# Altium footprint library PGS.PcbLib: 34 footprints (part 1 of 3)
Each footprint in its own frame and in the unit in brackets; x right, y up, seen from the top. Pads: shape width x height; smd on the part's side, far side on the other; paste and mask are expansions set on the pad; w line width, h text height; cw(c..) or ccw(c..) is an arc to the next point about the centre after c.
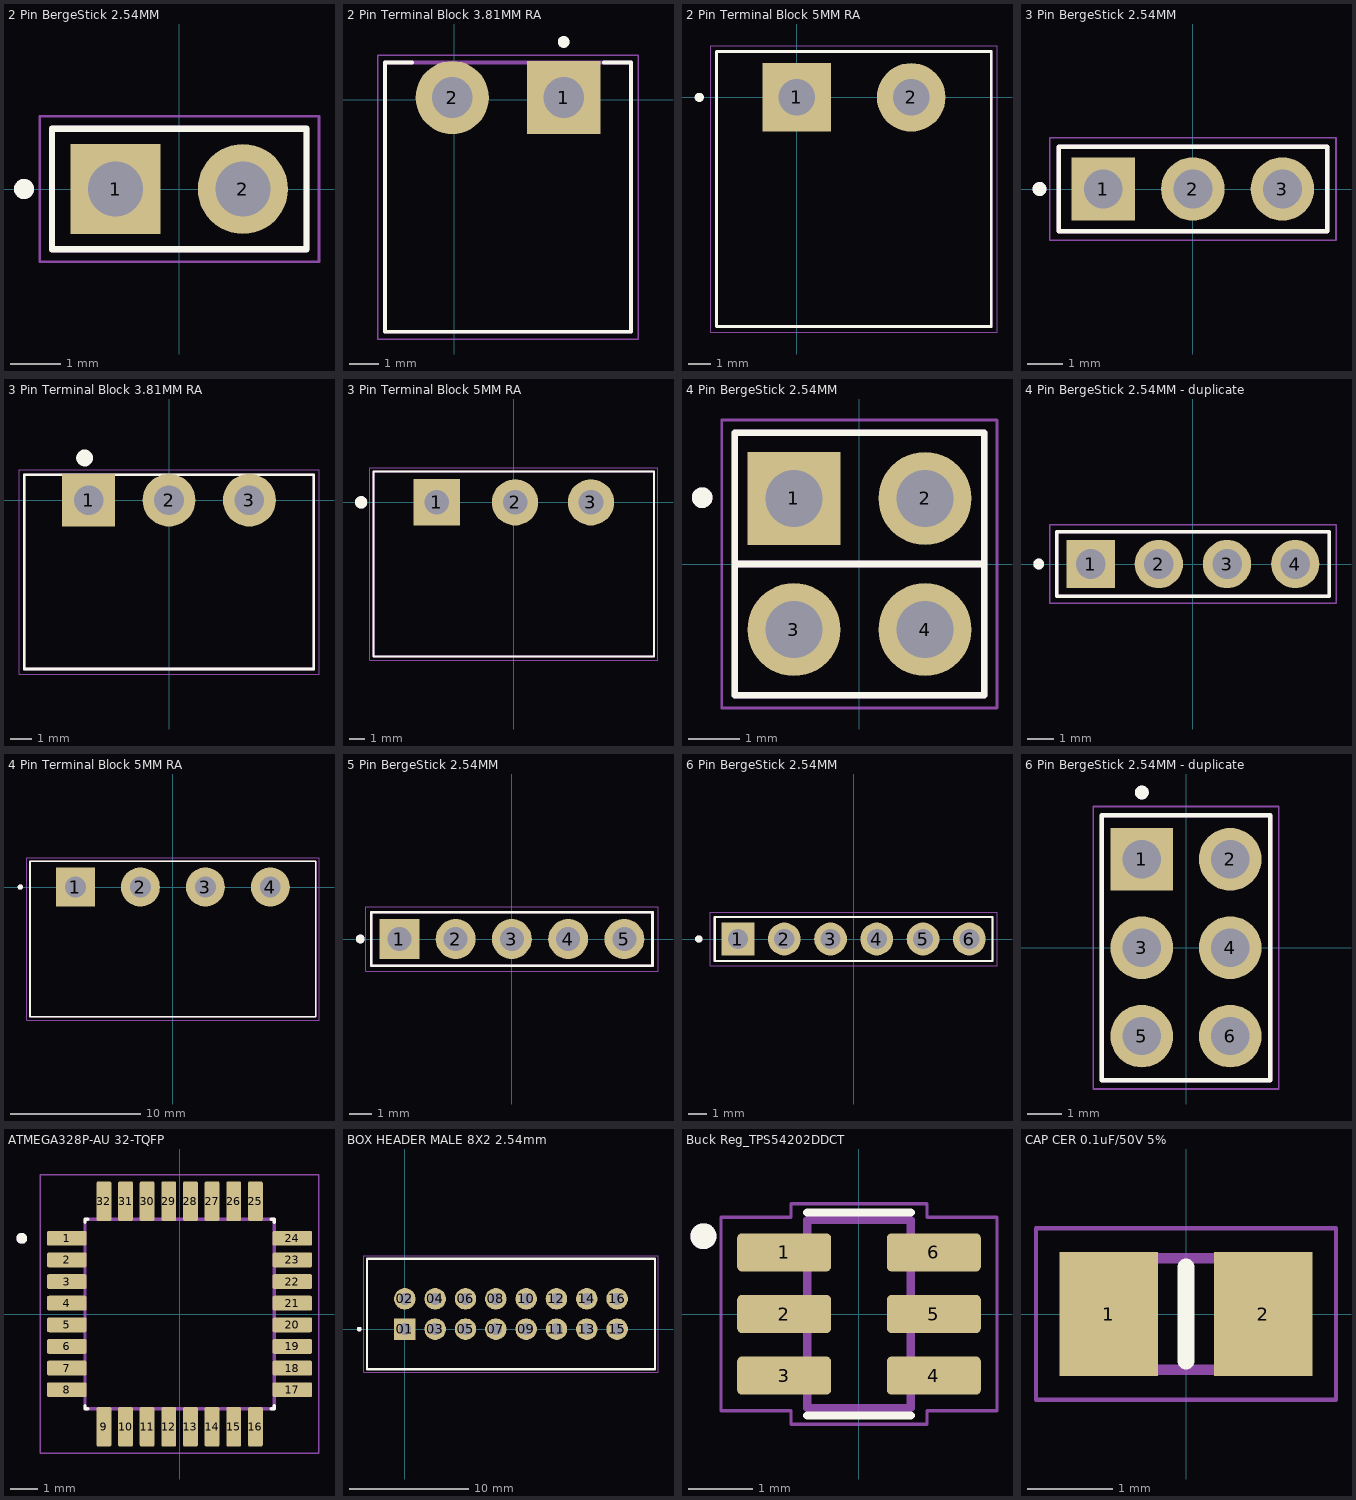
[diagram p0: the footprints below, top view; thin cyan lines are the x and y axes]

## 2 Pin BergeStick 2.54MM [mm] "2 Pin 2Pos THT S/T BergeStick 2.54MM Amphenol 68000-402HLF 3A AMPHENOL_68000-402HLF"
height 10.8
pads (2):
  rect 1.8x1.8 hole 1.1: 1(-1.27,0)
  round 1.8 hole 1.1: 2(1.27,0)
Top Overlay:
  circle w0.2: c-3.1,0 r0.1
  lines w0.127: -2.54,-1.205 2.54,-1.205 2.54,1.205 -2.54,1.205 -2.54,-1.205
Mechanical 13:
  circle w0.2: c-3.1,0 r0.1
  lines w0.127: -2.54,-1.205 2.54,-1.205 2.54,1.205 -2.54,1.205 -2.54,-1.205
Mechanical 15:
  lines w0.05: -2.79,-1.455 2.79,-1.455 2.79,1.455 -2.79,1.455 -2.79,-1.455
3D body "step_temp.STEP": height 8.39, standoff -2.41, extent -2.54,-1.205 2.54,1.205

## 2 Pin Terminal Block 3.81MM RA [mm] "2 Pin Terminal Block HDR 3.81MM THT RA TBP02R138102BE"
height 7.2
pads (2):
  rect 2.5x2.5 hole 1.4: 1(3.734,0.076)
  round 2.5 hole 1.4: 2(-0.076,0.076)
Top Overlay:
  circle w0.2: c3.734,1.976 r0.1
  lines w0.127: -1.446,1.276 -2.376,1.276 -2.376,-7.924 6.034,-7.924 6.034,1.276 5.104,1.276
Mechanical 13:
  circle w0.2: c3.734,1.976 r0.1
  lines w0.127: -2.376,-7.924 6.034,-7.924 6.034,1.276 -2.376,1.276 -2.376,-7.924
Mechanical 15:
  lines w0.05: -2.626,-8.174 6.284,-8.174 6.284,1.526 -2.626,1.526 -2.626,-8.174
3D body "step_temp.STEP": height 7.2, standoff -3.5, extent -2.39,-7.953 6.02,1.247

## 2 Pin Terminal Block 5MM RA [mm] "2 Pin Terminal Block HDR 5MM THT RA_OQ0271510000G"
height 8.5
pads (2):
  rect 3x3 hole 1.6: 1(0,0)
  round 3 hole 1.6: 2(5,0)
Top Overlay:
  circle w0.2: c-4.25,0 r0.1
  lines w0.127: -3.5,-10 -3.5,2 8.5,2 8.5,-10 -3.5,-10
Mechanical 13:
  circle w0.2: c-4.25,0 r0.1
  lines w0.127: -3.5,-10 -3.5,2 8.5,2 8.5,-10 -3.5,-10
Mechanical 15:
  lines w0.05: -3.75,-10.25 -3.75,2.25 8.75,2.25 8.75,-10.25 -3.75,-10.25
3D body "step_temp.STEP": height 8.5, standoff -3.5, extent -3.5,-10 8.5,2

## 3 Pin BergeStick 2.54MM [mm] "3 Pin 3Pos THT S/T BergeStick 2.54MM Amphenol 68001-403HLF 3A"
height 8.58
pads (3):
  rect 1.8x1.8 hole 1.1: 1(-2.54,0)
  round 1.8 hole 1.1: 2(0,0) 3(2.54,0)
Top Overlay:
  circle w0.2: c-4.35,0 r0.1
  lines w0.127: -3.81,-1.205 -3.81,1.205 3.81,1.205 3.81,-1.205 -3.81,-1.205
Mechanical 13:
  circle w0.2: c-4.35,0 r0.1
  lines w0.127: -3.81,-1.205 -3.81,1.205 3.81,1.205 3.81,-1.205 -3.81,-1.205
Mechanical 15:
  lines w0.05: -4.06,-1.455 -4.06,1.455 4.06,1.455 4.06,-1.455 -4.06,-1.455
3D body "step_temp.STEP": height 8.38, standoff -3.05, extent -3.81,-1.205 3.81,1.205

## 3 Pin Terminal Block 3.81MM RA [mm] "3 Pin Terminal Block HDR 3.81MM THT RA 284513-3"
pads (3):
  rect 2.5x2.5 hole 1.4: 1(-3.81,0)
  round 2.5 hole 1.4: 2(0,0) 3(3.81,0)
Top Overlay:
  circle w0.4: c-4,2 r0.2
  lines w0.127: -6.86,-8 -6.86,1.2 6.86,1.2 6.86,-8 -6.86,-8
Mechanical 13:
  lines w0.127: -6.86,-8 6.86,-8 6.86,1.2 -6.86,1.2 -6.86,-8
Mechanical 15:
  lines w0.05: -7.11,-8.25 7.11,-8.25 7.11,1.45 -7.11,1.45 -7.11,-8.25
3D body "step_temp.STEP": height 7.3, standoff -3.4, extent -6.86,-8.001 6.86,1.199

## 3 Pin Terminal Block 5MM RA [mm] "3 Pin Terminal Block HDR 5MM THT RA 231-433_001-000"
pads (3):
  rect 3x3 hole 1.6: 1(-5,0)
  round 3 hole 1.6: 2(0.08,0) 3(5,0)
Top Overlay:
  circle w0.4: c-9.91,0 r0.2
  lines w0.127: -9.1,-10 -9.1,2 9.1,2 9.1,-10 -9.1,-10
Mechanical 13:
  circle w0.4: c-9.906,0 r0.2
  lines w0.127: -9.1,-10 9.1,-10 9.1,2 -9.1,2 -9.1,-10
Mechanical 15:
  lines w0.05: -9.35,-10.25 -9.35,2.25 9.35,2.25 9.35,-10.25 -9.35,-10.25
3D body "2342079-3--3DModel-STEP-1.STEP": height 8.97, standoff -2.28, extent -8.418,-10.064 8.382,1.936

## 4 Pin BergeStick 2.54MM [mm] "4 Pin 2X2Pos THT S/T BergeStick 2.54MM Amphenol 67997-104HLF 3A AMPHENOL_67997-104HLF"
pads (4):
  rect 1.8x1.8 hole 1.1: 1(-1.27,1.27)
  round 1.8 hole 1.1: 2(1.27,1.27) 3(-1.27,-1.27) 4(1.27,-1.27)
Top Overlay:
  circle w0.2: c-3.048,1.285 r0.1
  lines w0.127: -2.413,0 2.413,0 ; -2.415,-2.54 2.415,-2.54 2.415,2.54 -2.415,2.54 -2.415,-2.54
Mechanical 13:
  circle w0.2: c-3.048,1.285 r0.1
  lines w0.127: -2.413,0 2.413,0 ; -2.415,-2.54 2.415,-2.54 ; -2.415,-2.54 -2.415,2.54 ; -2.415,-2.54 2.415,-2.54 ; -2.415,2.54 2.415,2.54 ; -2.415,2.54 2.415,2.54 ; 2.415,-2.54 2.415,2.54 ; 2.415,-2.54 2.415,2.54
Mechanical 15:
  lines w0.05: -2.665,-2.79 2.665,-2.79 2.665,2.79 -2.665,2.79 -2.665,-2.79
3D body "step_temp.STEP": height 8.38, standoff -3.05, extent -2.415,-2.54 2.415,2.54

## 4 Pin BergeStick 2.54MM - duplicate [mm] "4 Pin 4Pos THT S/T BergeStick 2.54MM Amphenol 68001-104HLF 3A AMPHENOL_68001-104HLF"
height 8.89
pads (4):
  rect 1.8x1.8 hole 1.1: 1(-3.81,0)
  round 1.8 hole 1.1: 2(-1.27,0) 3(1.27,0) 4(3.81,0)
Top Overlay:
  circle w0.2: c-5.75,0 r0.1
  lines w0.127: -5.08,-1.205 -5.08,1.205 5.08,1.205 5.08,-1.205 -5.08,-1.205
Mechanical 13:
  circle w0.2: c-5.75,0 r0.1
  lines w0.127: -5.08,-1.205 -5.08,1.205 5.08,1.205 5.08,-1.205 -5.08,-1.205
Mechanical 15:
  lines w0.05: -5.33,-1.455 -5.33,1.455 5.33,1.455 5.33,-1.455 -5.33,-1.455
3D body "step_temp.STEP": height 8.38, standoff -3.05, extent -5.08,-1.205 5.08,1.205

## 4 Pin Terminal Block 5MM RA [mm] "4 Pin Terminal Block HDR 5MM THT RA OQ0471510000G"
pads (4):
  rect 3x3 hole 1.6: 1(-7.5,0)
  round 3 hole 1.6: 2(-2.5,0) 3(2.5,0) 4(7.5,0)
Top Overlay:
  circle w0.2: c-11.75,0 r0.1
  lines w0.127: -11,-10 -11,2 11,2 11,-10 -11,-10
Mechanical 13:
  circle w0.2: c-11.75,0 r0.1
  lines w0.127: -11,-10 -11,2 11,2 11,-10 -11,-10
Mechanical 15:
  lines w0.05: -11.25,-10.25 -11.25,2.25 11.25,2.25 11.25,-10.25 -11.25,-10.25
3D body "796700-4--3DModel-STEP-510211.STEP": height 8.5, standoff -3.5, extent -11.254,-10.064 10.746,1.936

## 5 Pin BergeStick 2.54MM [mm] "5 Pin 5Pos THT S/T BergeStick 2.54MM Amphenol 68002-405HLF 3A AMPHENOL_68002-405HLF"
height 8.58
pads (5):
  rect 1.8x1.8 hole 1.092: 1(-5.08,0)
  round 1.8 hole 1.092: 2(-2.54,0) 3(0,0) 4(2.54,0) 5(5.08,0)
Top Overlay:
  circle w0.2: c-6.85,0 r0.1
  lines w0.127: -6.35,-1.206 -6.35,1.206 6.35,1.206 6.35,-1.206 -6.35,-1.206
Mechanical 13:
  circle w0.2: c-6.85,0 r0.1
  lines w0.127: -6.35,-1.206 -6.35,1.206 6.35,1.206 6.35,-1.206 -6.35,-1.206
Mechanical 15:
  lines w0.05: -6.6,-1.456 6.6,-1.456 6.6,1.456 -6.6,1.456 -6.6,-1.456
3D body "step_temp.STEP": height 8.38, standoff -3.81, extent -6.35,-1.205 6.35,1.205

## 6 Pin BergeStick 2.54MM [mm] "6 Pin 6Pos THT S/T BergeStick 2.54MM Amphenol 68604-406HLF 3A AMPHENOL_68604-406HLF"
height 12.198
pads (6):
  rect 1.8x1.8 hole 1.1: 1(-6.35,0)
  round 1.8 hole 1.1: 2(-3.81,0) 3(-1.27,0) 4(1.27,0) 5(3.81,0) 6(6.35,0)
Top Overlay:
  circle w0.2: c-8.5,0 r0.1
  lines w0.127: -7.62,-1.205 -7.62,1.205 7.62,1.205 7.62,-1.205 -7.62,-1.205
Mechanical 13:
  circle w0.2: c-8.5,0 r0.1
  lines w0.127: -7.62,-1.205 -7.62,1.205 7.62,1.205 7.62,-1.205 -7.62,-1.205
Mechanical 15:
  lines w0.05: -7.87,-1.455 7.87,-1.455 7.87,1.455 -7.87,1.455 -7.87,-1.455
3D body "step_temp.STEP": height 12.19, standoff -3.05, extent -7.62,-1.205 7.62,1.205

## 6 Pin BergeStick 2.54MM - duplicate [mm] "6 Pin 3X3Pos THT S/T BergeStick 2.54MM Amphenol 69192-406HLF AMPHENOL_69192-406HLF"
pads (6):
  rect 1.8x1.8 hole 1.1: 1(-1.27,2.54)
  round 1.8 hole 1.1: 2(1.27,2.54) 3(-1.27,0) 4(1.27,0) 5(-1.27,-2.54) 6(1.27,-2.54)
Top Overlay:
  circle w0.2: c-1.27,4.46 r0.1
  lines w0.127: -2.415,-3.81 -2.415,3.81 2.415,3.81 2.415,-3.81 -2.415,-3.81
Mechanical 13:
  circle w0.2: c-1.27,4.46 r0.1
  lines w0.127: -2.415,-3.81 2.415,-3.81 ; -2.415,-3.81 -2.415,3.81 ; -2.415,-3.81 2.415,-3.81 ; -2.415,3.81 2.415,3.81 ; -2.415,3.81 2.415,3.81 ; 2.415,-3.81 2.415,3.81 ; 2.415,-3.81 2.415,3.81
Mechanical 15:
  lines w0.05: -2.665,-4.06 -2.665,4.06 2.665,4.06 2.665,-4.06 -2.665,-4.06
3D body "step_temp.STEP": height 8.38, standoff -3.05, extent -2.415,-3.81 2.415,3.81

## ATMEGA328P-AU 32-TQFP [mm] "AVR AVRÂ® ATmega Microcontroller IC 8-Bit 20MHz 32KB (16K x 16) FLASH 32-TQFP SMT (7x7)QFP80P900X900X120-32N"
height 1.2
pads (32):
  rrect25% 1.47x0.55 smd: 1(-4.17,2.8) 2(-4.17,2) 3(-4.17,1.2) 4(-4.17,0.4) 5(-4.17,-0.4) 6(-4.17,-1.2) 7(-4.17,-2) 8(-4.17,-2.8) 17(4.17,-2.8) 18(4.17,-2) 19(4.17,-1.2) 20(4.17,-0.4) 21(4.17,0.4) 22(4.17,1.2) 23(4.17,2) 24(4.17,2.8)
  rrect25% 0.55x1.47 smd: 9(-2.8,-4.17) 10(-2,-4.17) 11(-1.2,-4.17) 12(-0.4,-4.17) 13(0.4,-4.17) 14(1.2,-4.17) 15(2,-4.17) 16(2.8,-4.17) 25(2.8,4.17) 26(2,4.17) 27(1.2,4.17) 28(0.4,4.17) 29(-0.4,4.17) 30(-1.2,4.17) 31(-2,4.17) 32(-2.8,4.17)
Top Overlay:
  circle w0.2: c-5.84,2.8 r0.1
  lines w0.127: -3.5,-3.395 -3.5,-3.5 -3.395,-3.5 ; -3.5,3.395 -3.5,3.5 -3.395,3.5 ; 3.395,-3.5 3.5,-3.5 3.5,-3.395 ; 3.395,3.5 3.5,3.5 3.5,3.395
Mechanical 13:
  circle w0.2: c-5.84,2.8 r0.1
  lines w0.127: -3.5,-3.5 3.5,-3.5 3.5,3.5 -3.5,3.5 -3.5,-3.5
Mechanical 15:
  lines w0.05: -5.155,-5.155 5.155,-5.155 5.155,5.155 -5.155,5.155 -5.155,-5.155
3D body "step_temp.STEP": height 1.2, standoff 0, extent -4.5,-4.5 4.5,4.5

## BOX HEADER MALE 8X2 2.54mm [mm] "THT S/T Straight BOX HEADER MALE 8X2 2.54mm 16 pin"
pads (16):
  rect 1.8x1.8 hole 1.02: 01(0,0)
  round 1.8 hole 1.02: 02(0,2.54) 03(2.54,0) 04(2.54,2.54) 05(5.08,0) 06(5.08,2.54) 07(7.62,0) 08(7.62,2.54) 09(10.16,0) 10(10.16,2.54) 11(12.7,0) 12(12.7,2.54) 13(15.24,0) 14(15.24,2.54) 15(17.78,0) 16(17.78,2.54)
Top Overlay:
  circle w0.2: c-3.825,0 r0.1
  lines w0.2: -3.175,-3.365 20.955,-3.365 20.955,5.905 -3.175,5.905 -3.175,-3.365
Mechanical 13:
  circle w0.2: c-3.825,0 r0.1
  lines w0.1: -3.175,-3.365 20.955,-3.365 20.955,5.905 -3.175,5.905 -3.175,-3.365
Mechanical 15:
  lines w0.05: -3.425,-3.615 21.205,-3.615 21.205,6.155 -3.425,6.155 -3.425,-3.615
3D body "52601-S16-4LF--3DModel-STEP-510211.STEP": height 9.53, standoff -3.3, extent -4.953,-3.048 22.733,5.715

## Buck Reg_TPS54202DDCT [mm] "4.5V to 28V Input, 2A Output, EMI Friendly Synchronous Step-Down SMT Converter TPS54202DDCT"
pads (6):
  rrect25% 1.45x0.59 smd: 1(-1.155,0.95) 2(-1.155,0) 3(-1.155,-0.95) 4(1.155,-0.95) 5(1.155,0) 6(1.155,0.95)
Top Overlay:
  circle w0.2: c-2.4,1.2 r0.1
  lines w0.127: -0.8,-1.565 0.8,-1.565 ; -0.8,1.565 0.8,1.565
Mechanical 13:
  circle w0.2: c-2.4,1.2 r0.1
  lines w0.127: -0.8,-1.45 0.8,-1.45 0.8,1.45 -0.8,1.45 -0.8,-1.45
Mechanical 15:
  lines w0.05: -2.13,-1.495 -1.05,-1.495 -1.05,-1.7 1.05,-1.7 1.05,-1.495 2.13,-1.495 2.13,1.495 1.05,1.495 1.05,1.7 -1.05,1.7 -1.05,1.495 -2.13,1.495 -2.13,-1.495
3D body "step_temp.STEP": height 1.1, standoff 0, extent -1.4,-1.45 1.4,1.45

## CAP CER 0.1uF/50V 5% [mm] "CAP CER 0.1uF/50V  Ceramic Capacitor X7R 0805 (2012 Metric) SMT"
pads (2):
  rect 1.15x1.45 smd: 1(-0.9,0) 2(0.9,0)
Top Overlay:
  lines w0.2: 0,-0.55 0,0.55
Mechanical 13:
  region: -0.5,-0.65 -1,-0.65 -1,0.65 -0.5,0.65
  region: 1,-0.65 0.5,-0.65 0.5,0.65 1,0.65
  lines w0.127: -1,-0.65 1,-0.65 1,0.65 -1,0.65 -1,-0.65
Mechanical 15:
  lines w0.05: -1.75,-1 1.75,-1 1.75,1 -1.75,1 -1.75,-1
3D body "step_temp.STEP": height 1.35, standoff 0, extent -1,-0.625 1,0.625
